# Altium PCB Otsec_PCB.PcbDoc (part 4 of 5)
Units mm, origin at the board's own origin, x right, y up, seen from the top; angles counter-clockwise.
Board outline 170 x 120 mm, 3 copper layers (Top Layer, Internal Plane 1, Bottom Layer), stack 1.608 mm thick; 1624 components, 0 nets, 5478 pads, 0 vias.
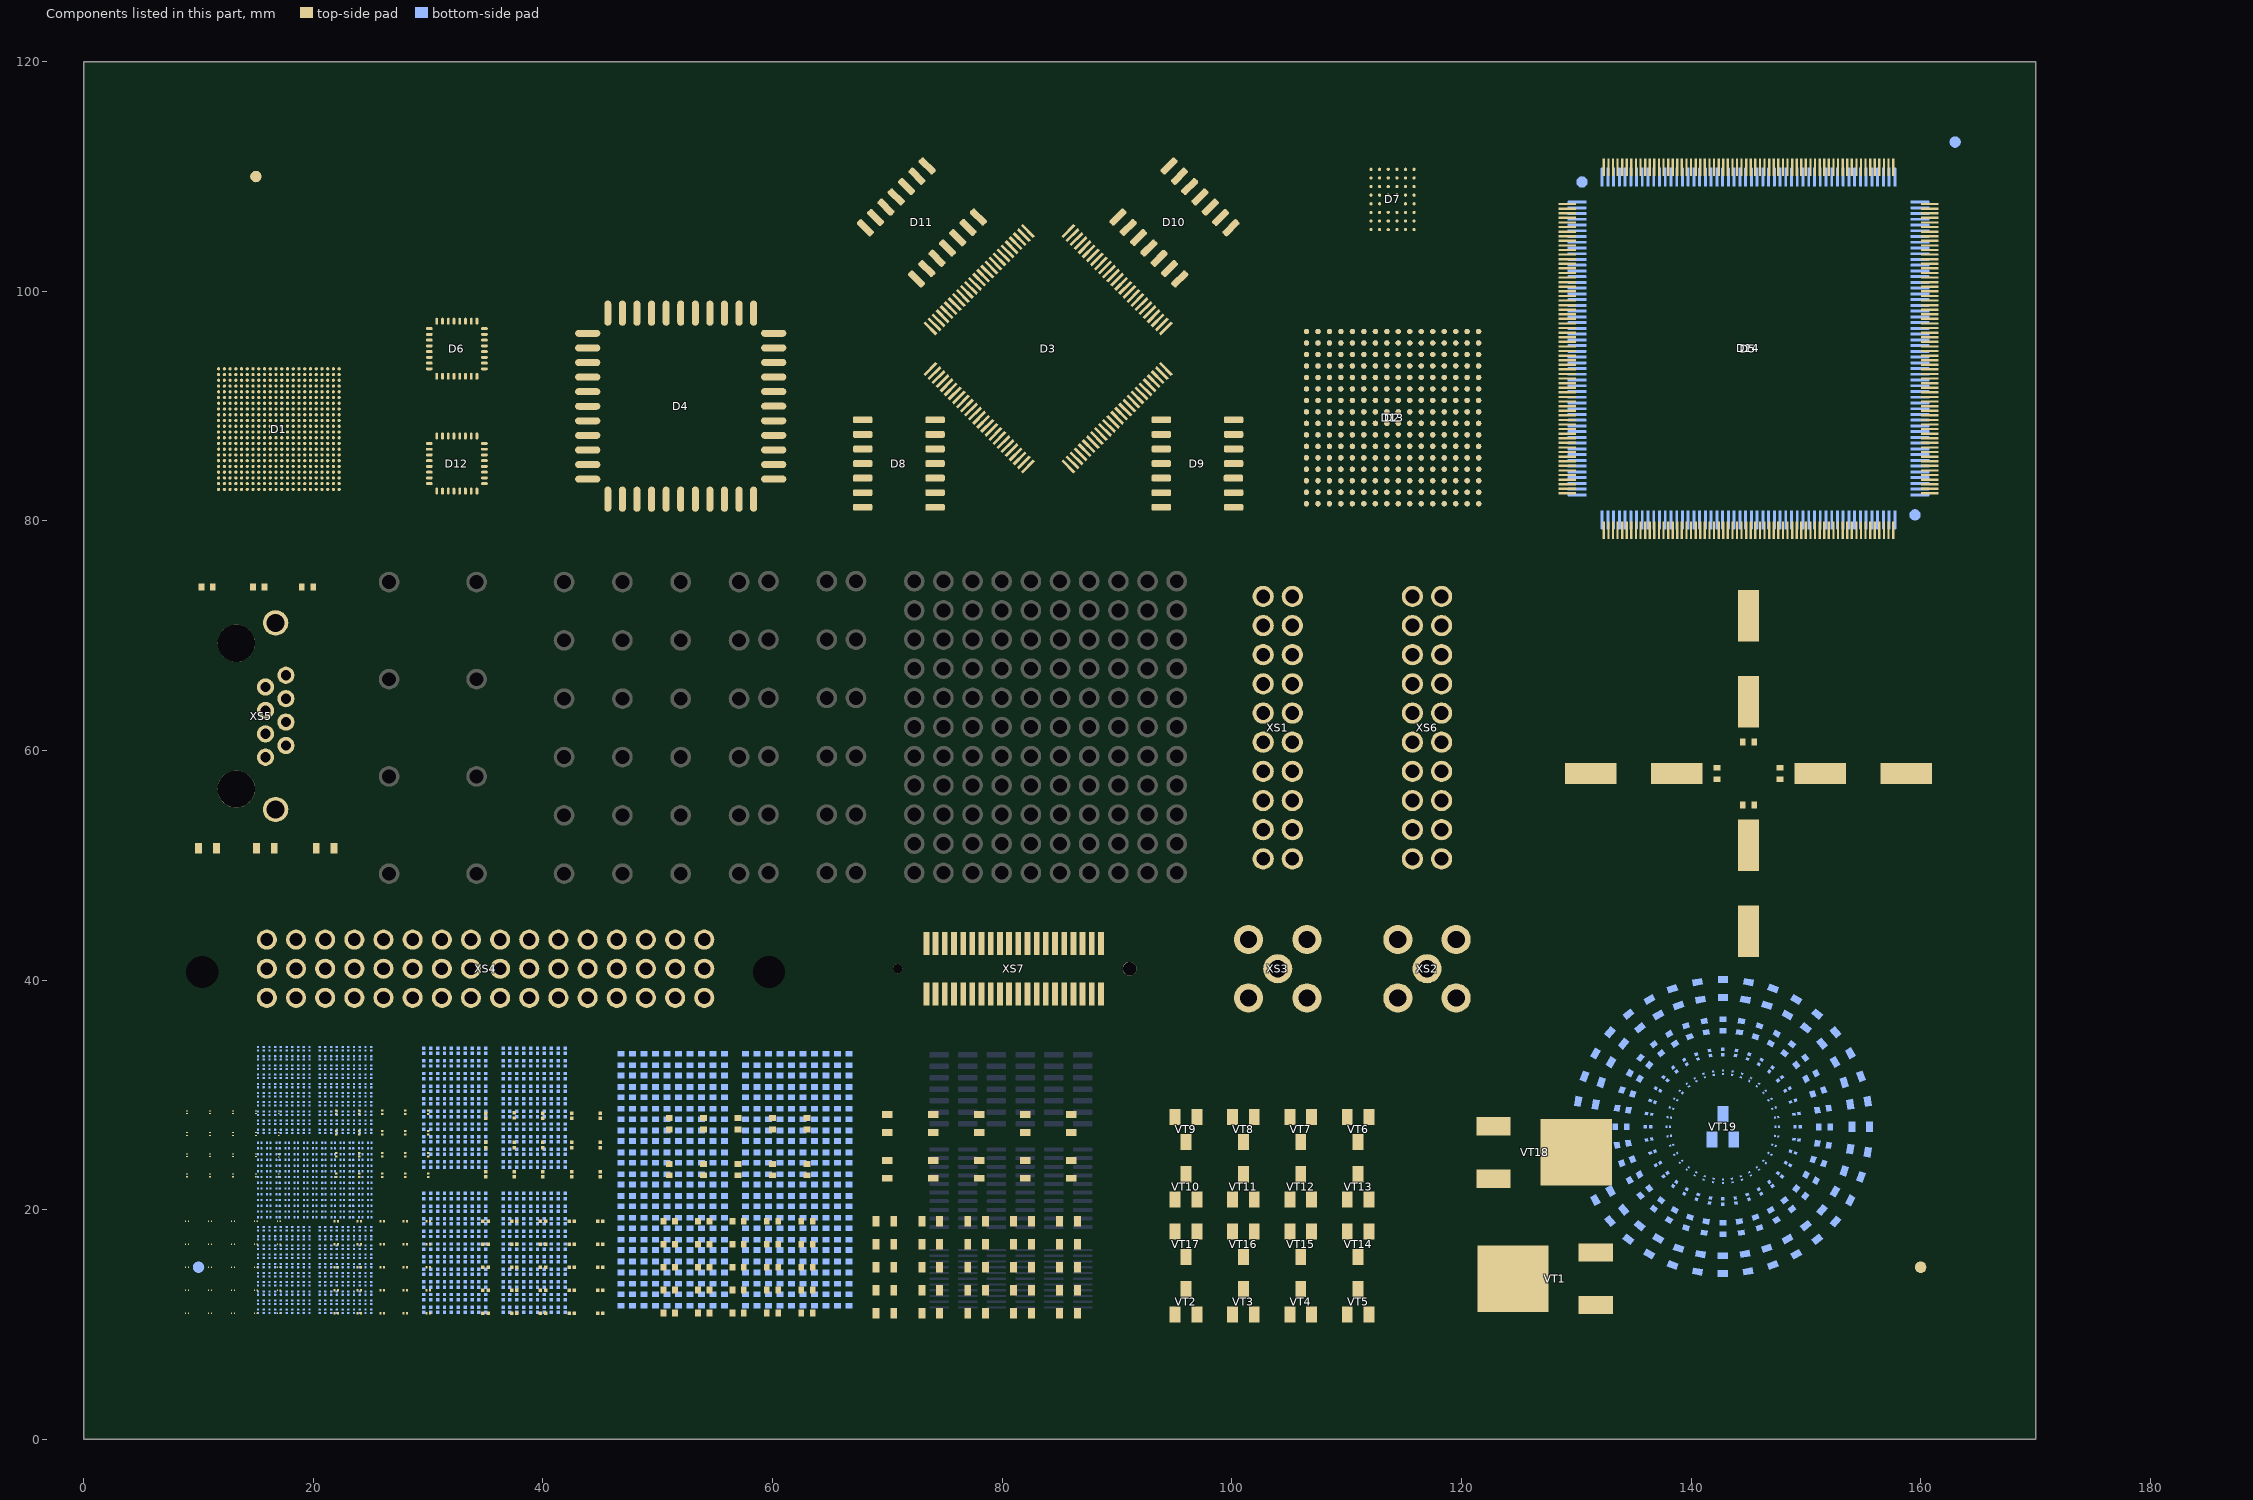
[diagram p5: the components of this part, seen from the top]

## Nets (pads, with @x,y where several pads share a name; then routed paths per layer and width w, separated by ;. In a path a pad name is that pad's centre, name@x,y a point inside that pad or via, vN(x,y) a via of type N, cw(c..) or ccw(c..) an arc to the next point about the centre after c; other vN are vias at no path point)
pads on no net: C1.1 C1.2 C2.1 C2.2 C3.1 C3.2 C4.1 C4.2 D1.1 D1.2 D1.3 D1.4 D1.5 D1.6 D1.7 D1.8 D1.9 D1.10 D1.11 D1.12 D1.13 D1.14 D1.15 D1.16 D1.17 D1.18 D1.19 D1.20 D1.21 D1.22 D1.23 D1.24 D1.25 D1.26 D1.27 D1.28 D1.29 D1.30 D1.31 D1.32 D1.33 D1.34 D1.35 D1.36 D1.37 D1.38 D1.39 D1.40 D1.41 D1.42 D1.43 D1.44 D1.45 D1.46 D1.47 D1.48 D1.49 D1.50 D1.51 D1.52 D1.53 D1.54 D1.55 D1.56 D1.57 D1.58 D1.59 D1.60 D1.61 D1.62 D1.63 D1.64 D1.65 D1.66 D1.67 D1.68 D1.69 D1.70 D1.71 D1.72 D1.73 D1.74 D1.75 D1.76 D1.77 D1.78 D1.79 D1.80 D1.81 D1.82 D1.83 D1.84 D1.85 D1.86 D1.87 D1.88 D1.89 D1.90 D1.91 D1.92 D1.93 D1.94 D1.95 D1.96 D1.97 D1.98 D1.99 D1.100 D1.101 D1.102 D1.103 D1.104 D1.105 D1.106 D1.107 D1.108 D1.109 D1.110 D1.111 D1.112 D1.113 D1.114 D1.115 D1.116 D1.117 D1.118 D1.119 D1.120 D1.121 D1.122 D1.123 D1.124 D1.125 D1.126 D1.127 D1.128 D1.129 D1.130 D1.131 D1.132 D1.133 D1.134 D1.135 D1.136 D1.137 D1.138 D1.139 D1.140 D1.141 D1.142 D1.143 D1.144 D1.145 D1.146 D1.147 D1.148 D1.149 D1.150 D1.151 D1.152 D1.153 D1.154 D1.155 D1.156 D1.157 D1.158 D1.159 D1.160 D1.161 D1.162 D1.163 D1.164 D1.165 D1.166 D1.167 D1.168 D1.169 D1.170 D1.171 D1.172 D1.173 D1.174 D1.175 D1.176 D1.177 D1.178 D1.179 D1.180 D1.181 D1.182 D1.183 D1.184 D1.185 D1.186 D1.187 D1.188 D1.189 D1.190 D1.191 D1.192 D1.193 D1.194 D1.195 D1.196 D1.197 D1.198 D1.199 D1.200 D1.201 D1.202 D1.203 D1.204 D1.205 D1.206 D1.207 D1.208 D1.209 D1.210 D1.211 D1.212 D1.213 D1.214 D1.215 D1.216 D1.217 D1.218 D1.219 D1.220 D1.221 D1.222 D1.223 D1.224 D1.225 D1.226 D1.227 D1.228 D1.229 D1.230 D1.231 D1.232 D1.233 D1.234 D1.235 D1.236 D1.237 D1.238 D1.239 D1.240 D1.241 D1.242 D1.243 D1.244 D1.245 D1.246 D1.247 D1.248 D1.249 D1.250 D1.251 D1.252 D1.253 D1.254 D1.255 D1.256 D1.257 D1.258 D1.259 D1.260 D1.261 D1.262 D1.263 D1.264 D1.265 D1.266 D1.267 D1.268 D1.269 D1.270 D1.271 D1.272 D1.273 D1.274 D1.275 D1.276 D1.277 D1.278 D1.279 D1.280 D1.281 D1.282 D1.283 D1.284 D1.285 D1.286 D1.287 D1.288 D1.289 D1.290 D1.291 D1.292 D1.293 D1.294 D1.295 D1.296 D1.297 D1.298 D1.299 D1.300 D1.301 D1.302 D1.303 D1.304 D1.305 D1.306 D1.307 D1.308 D1.309 D1.310 D1.311 D1.312 D1.313 D1.314 D1.315 D1.316 D1.317 D1.318 D1.319 D1.320 D1.321 D1.322 D1.323 D1.324 D1.325 D1.326 D1.327 D1.328 D1.329 D1.330 D1.331 D1.332 D1.333 D1.334 D1.335 D1.336 D1.337 D1.338 D1.339 D1.340 D1.341 D1.342 D1.343 D1.344 D1.345 D1.346 D1.347 D1.348 D1.349 D1.350 D1.351 D1.352 D1.353 D1.354 D1.355 D1.356 D1.357 D1.358 D1.359 D1.360 D1.361 D1.362 D1.363 D1.364 D1.365 D1.366 D1.367 D1.368 D1.369 D1.370 D1.371 D1.372 D1.373 D1.374 D1.375 D1.376 D1.377 D1.378 D1.379 D1.380 D1.381 D1.382 D1.383 D1.384 D1.385 D1.386 D1.387 D1.388 D1.389 D1.390 D1.391 D1.392 D1.393 D1.394 D1.395 D1.396 D1.397 D1.398 D1.399 D1.400 D1.401 D1.402 D1.403 D1.404 D1.405 D1.406 D1.407 D1.408 D1.409 D1.410 D1.411 D1.412 D1.413 D1.414 D1.415 D1.416 D1.417 D1.418 D1.419 D1.420 D1.421 D1.422 D1.423 D1.424 D1.425 D1.426 D1.427 D1.428 D1.429 D1.430 D1.431 D1.432 D1.433 D1.434 D1.435 D1.436 D1.437 D1.438 D1.439 D1.440 D1.441 D1.442 D1.443 D1.444 D1.445 D1.446 D1.447 D1.448 D1.449 D1.450 D1.451 D1.452 D1.453 D1.454 D1.455 D1.456 D1.457 D1.458 D1.459 D1.460 D1.461 D1.462 D1.463 D1.464 D1.465 D1.466 D1.467 D1.468 D1.469 D1.470 D1.471 D1.472 D1.473 D1.474 D1.475 D1.476 D1.477 D1.478 D1.479 D1.480 D1.481 D1.482 D1.483 D1.484 D2.1 D2.2 D2.3 D2.4 D2.5 D2.6 D2.7 D2.8 D2.9 D2.10 D2.11 D2.12 D2.13 D2.14 D2.15 D2.16 D2.17 D2.18 D2.19 D2.20 D2.21 D2.22 D2.23 D2.24 D2.25 D2.26 D2.27 D2.28 D2.29 D2.30 D2.31 D2.32 D2.33 D2.34 D2.35 D2.36 D2.37 D2.38 D2.39 D2.40 D2.41 D2.42 D2.43 D2.44 D2.45 D2.46 D2.47 D2.48 D2.49 D2.50 D2.51 D2.52 D2.53 D2.54 D2.55 D2.56 D2.57 D2.58 D2.59 D2.60 D2.61 D2.62 D2.63 D2.64 D2.65 D2.66 D2.67 D2.68 D2.69 D2.70 D2.71 D2.72 D2.73 D2.74 D2.75 D2.76 D2.77 D2.78 D2.79 D2.80 D2.81 D2.82 D2.83 D2.84 D2.85 D2.86 D2.87 D2.88 D2.89 D2.90 D2.91 D2.92 D2.93 D2.94 D2.95 D2.96 D2.97 D2.98 D2.99 D2.100 D2.101 D2.102 D2.103 D2.104 D2.105 D2.106 D2.107 D2.108 D2.109 D2.110 D2.111 D2.112 D2.113 D2.114 D2.115 D2.116 D2.117 D2.118 D2.119 D2.120 D2.121 D2.122 D2.123 D2.124 D2.125 D2.126 D2.127 D2.128 D2.129 D2.130 D2.131 D2.132 D2.133 D2.134 D2.135 D2.136 D2.137 D2.138 D2.139 D2.140 D2.141 D2.142 D2.143 D2.144 D2.145 D2.146 D2.147 D2.148 D2.149 D2.150 D2.151 D2.152 D2.153 D2.154 D2.155 D2.156 D2.157 D2.158 D2.159 D2.160 D2.161 D2.162 D2.163 D2.164 D2.165 D2.166 D2.167 D2.168 D2.169 D2.170 D2.171 D2.172 D2.173 D2.174 D2.175 D2.176 D2.177 D2.178 D2.179 D2.180 D2.181 D2.182 D2.183 D2.184 D2.185 D2.186 D2.187 D2.188 D2.189 D2.190 D2.191 D2.192 D2.193 D2.194 D2.195 D2.196 D2.197 D2.198 D2.199 D2.200 D2.201 D2.202 D2.203 D2.204 D2.205 D2.206 D2.207 D2.208 D2.209 D2.210 D2.211 D2.212 D2.213 D2.214 D2.215 D2.216 D2.217 D2.218 D2.219 D2.220 D2.221 D2.222 D2.223 D2.224 D2.225 D2.226 D2.227 D2.228 D2.229 D2.230 D2.231 D2.232 D2.233 D2.234 D2.235 D2.236 D2.237 D2.238 D2.239 D2.240 D2.241 D2.242 D2.243 D2.244 D2.245 D2.246 D2.247 D2.248 D2.249 D2.250 D2.251 D2.252 D2.253 D2.254 D2.255 D2.256 D3.1 D3.2 D3.3 D3.4 D3.5 D3.6 D3.7 D3.8 D3.9 D3.10 D3.11 D3.12 D3.13 D3.14 D3.15 D3.16 D3.17 D3.18 D3.19 D3.20 D3.21 D3.22 D3.23 D3.24 D3.25 D3.26 D3.27 D3.28 D3.29 D3.30 D3.31 D3.32 D3.33 D3.34 D3.35 D3.36 D3.37 D3.38 D3.39 D3.40 D3.41 D3.42 D3.43 D3.44 D3.45 D3.46 D3.47 D3.48 D3.49 D3.50 D3.51 D3.52 D3.53 D3.54 D3.55 D3.56 D3.57 D3.58 D3.59 D3.60 D3.61 D3.62 D3.63 D3.64 D3.65 D3.66 D3.67 D3.68 D3.69 D3.70 D3.71 D3.72 D3.73 D3.74 D3.75 D3.76 D3.77 D3.78 D3.79 D3.80 D3.81 D3.82 D3.83 D3.84 D3.85 D3.86 D3.87 D3.88 D3.89 D3.90 D3.91 D3.92 D3.93 D3.94 D3.95 D3.96 D3.97 D3.98 D3.99 D3.100 D4.1 D4.2 D4.3 D4.4 D4.5 D4.6 D4.7 D4.8 D4.9 D4.10 D4.11 D4.12 D4.13 D4.14 D4.15 D4.16 D4.17 D4.18 D4.19 D4.20 D4.21 D4.22 D4.23 D4.24 D4.25 D4.26 D4.27 D4.28 D4.29 D4.30 D4.31 D4.32 D4.33 D4.34 D4.35 D4.36 D4.37 D4.38 D4.39 D4.40 D4.41 D4.42 D4.43 D4.44 D5.1 D5.2 D5.3 D5.4 D5.5 D5.6 D5.7 D5.8 D5.9 D5.10 D5.11 D5.12 D5.13 D5.14 D5.15 D5.16 D5.17 D5.18 D5.19 D5.20 D5.21 D5.22 D5.23 D5.24 D5.25 D5.26 D5.27 D5.28 D5.29 D5.30 D5.31 D5.32 D5.33 D5.34 D5.35 D5.36 D5.37 D5.38 D5.39 D5.40 D5.41 D5.42 D5.43 D5.44 D5.45 D5.46 D5.47 D5.48 D5.49 D5.50 D5.51 D5.52 D5.53 D5.54 D5.55 D5.56 D5.57 D5.58 D5.59 D5.60 D5.61 D5.62 D5.63 D5.64 D5.65 D5.66 D5.67 D5.68 D5.69 D5.70 D5.71 D5.72 D5.73 D5.74 D5.75 D5.76 D5.77 D5.78 D5.79 D5.80 D5.81 D5.82 D5.83 D5.84 D5.85 D5.86 D5.87 D5.88 D5.89 D5.90 D5.91 D5.92 D5.93 D5.94 D5.95 D5.96 D5.97 D5.98 D5.99 D5.100 D5.101 D5.102 D5.103 D5.104 D5.105 D5.106 D5.107 D5.108 D5.109 D5.110 D5.111 D5.112 D5.113 D5.114 D5.115 D5.116 D5.117 D5.118 D5.119 D5.120 D5.121 D5.122 D5.123 D5.124 D5.125 D5.126 D5.127 D5.128 D5.129 D5.130 D5.131 D5.132 D5.133 D5.134 D5.135 D5.136 D5.137 D5.138 D5.139 D5.140 D5.141 D5.142 D5.143 D5.144 D5.145 D5.146 D5.147 D5.148 D5.149 D5.150 D5.151 D5.152 D5.153 D5.154 D5.155 D5.156 D5.157 D5.158 D5.159 D5.160 D5.161 D5.162 D5.163 D5.164 D5.165 D5.166 D5.167 D5.168 D5.169 D5.170 D5.171 D5.172 D5.173 D5.174 D5.175 D5.176 D5.177 D5.178 D5.179 D5.180 D5.181 D5.182 D5.183 D5.184 D5.185 D5.186 D5.187 D5.188 D5.189 D5.190 D5.191 D5.192 D5.193 D5.194 D5.195 D5.196 D5.197 D5.198 D5.199 D5.200 D5.201 D5.202 D5.203 D5.204 D5.205 D5.206 D5.207 D5.208 D5.209 D5.210 D5.211 D5.212 D5.213 D5.214 D5.215 D5.216 D5.217 D5.218 D5.219 D5.220 D5.221 D5.222 D5.223 D5.224 D5.225 D5.226 D5.227 D5.228 D5.229 D5.230 D5.231 D5.232 D5.233 D5.234 D5.235 D5.236 D5.237 D5.238 D5.239 D5.240 D5.241 D5.242 D5.243 D5.244 D5.245 D5.246 D5.247 D5.248 D5.249 D5.250 D5.251 D5.252 D5.253 D5.254 D5.255 D5.256 D6.1 D6.2 D6.3 D6.4 D6.5 D6.6 D6.7 D6.8 D6.9 D6.10 D6.11 D6.12 D6.13 D6.14 D6.15 D6.16 D6.17 D6.18 D6.19 D6.20 D6.21 D6.22 D6.23 D6.24 D6.25 D6.26 D6.27 D6.28 D6.29 D6.30 D6.31 D6.32 D7.1 D7.2 D7.3 D7.4 D7.5 D7.6 D7.7 D7.8 D7.9 D7.10 D7.11 D7.12 D7.13 D7.14 D7.15 D7.16 D7.17 D7.18 D7.19 D7.20 D7.21 D7.22 D7.23 D7.24 D7.25 D7.26 D7.27 D7.28 D7.29 D7.30 D7.31 D7.32 D7.33 D7.34 D7.35 D7.36 D7.37 D7.38 D7.39 D7.40 D7.41 D7.42 D7.43 D7.44 D7.45 D7.46 D8.1 D8.2 D8.3 D8.4 D8.5 D8.6 D8.7 D8.8 D8.9 D8.10 D8.11 D8.12 D8.13 D8.14 D9.1 D9.2 D9.3 D9.4 D9.5 D9.6 D9.7 D9.8 D9.9 D9.10 D9.11 D9.12 D9.13 D9.14 D10.1 D10.2 D10.3 D10.4 D10.5 D10.6 D10.7 D10.8 D10.9 D10.10 D10.11 D10.12 D10.13 D10.14 D11.1 D11.2 D11.3 D11.4 D11.5 D11.6 D11.7 D11.8 D11.9 D11.10 D11.11 D11.12 D11.13 D11.14 D12.1 D12.2 D12.3 D12.4 D12.5 D12.6 D12.7 D12.8 D12.9 D12.10 D12.11 D12.12 D12.13 D12.14 D12.15 D12.16 D12.17 D12.18 D12.19 D12.20 D12.21 D12.22 D12.23 D12.24 D12.25 D12.26 D12.27 D12.28 D12.29 D12.30 D12.31 D12.32 D13.1 D13.2 D13.3 D13.4 D13.5 D13.6 D13.7 D13.8 D13.9 D13.10 D13.11 D13.12 D13.13 D13.14 D13.15 D13.16 D13.17 D13.18 D13.19 D13.20 D13.21 D13.22 D13.23 D13.24 D13.25 D13.26 D13.27 D13.28 D13.29 D13.30 D13.31 D13.32 D13.33 D13.34 D13.35 D13.36 D13.37 D13.38 D13.39 D13.40 D13.41 D13.42 D13.43 D13.44 D13.45 D13.46 D13.47 D13.48 D13.49 D13.50 D13.51 D13.52 D13.53 D13.54 D13.55 D13.56 D13.57 D13.58 D13.59 D13.60 D13.61 D13.62 D13.63 D13.64 D13.65 D13.66 D13.67 D13.68 D13.69 D13.70 D13.71 D13.72 D13.73 D13.74 D13.75 D13.76 D13.77 D13.78 D13.79 D13.80 D13.81 D13.82 D13.83 D13.84 D13.85 D13.86 D13.87 D13.88 D13.89 D13.90 D13.91 D13.92 D13.93 D13.94 D13.95 D13.96 D13.97 D13.98 D13.99 D13.100 D13.101 D13.102 D13.103 D13.104 D13.105 D13.106 D13.107 D13.108 D13.109 D13.110 D13.111 D13.112 D13.113 D13.114 D13.115 D13.116 D13.117 D13.118 D13.119 D13.120 D13.121 D13.122 D13.123 D13.124 D13.125 D13.126 D13.127 D13.128 D13.129 D13.130 D13.131 D13.132 D13.133 D13.134 D13.135 D13.136 D13.137 D13.138 D13.139 D13.140 D13.141 D13.142 D13.143 D13.144 D13.145 D13.146 D13.147 D13.148 D13.149 D13.150 D13.151 D13.152 D13.153 D13.154 D13.155 D13.156 D13.157 D13.158 D13.159 D13.160 D13.161 D13.162 D13.163 D13.164 D13.165 D13.166 D13.167 D13.168 D13.169 D13.170 D13.171 D13.172 D13.173 D13.174 D13.175 D13.176 D13.177 D13.178 D13.179 D13.180 D13.181 D13.182 D13.183 D13.184 D13.185 D13.186 D13.187 D13.188 D13.189 D13.190 D13.191 D13.192 D13.193 D13.194 D13.195 D13.196 D13.197 D13.198 D13.199 D13.200 D13.201 D13.202 D13.203 D13.204 D13.205 D13.206 D13.207 D13.208 D13.209 D13.210 D13.211 D13.212 D13.213 D13.214 D13.215 D13.216 D13.217 D13.218 D13.219 D13.220 D13.221 D13.222 D13.223 D13.224 D13.225 D13.226 D13.227 D13.228 D13.229 D13.230 D13.231 D13.232 D13.233 D13.234 D13.235 D13.236 D13.237 D13.238 D13.239 D13.240 D13.241 D13.242 D13.243 D13.244 D13.245 D13.246 D13.247 D13.248 D13.249 D13.250 D13.251 D13.252 D13.253 D13.254 D13.255 D13.256 D14. D14.1 D14.2 D14.3 D14.4 D14.5 D14.6 D14.7 D14.8 D14.9 D14.10 D14.11 D14.12 D14.13 D14.14 D14.15 D14.16 D14.17 D14.18 D14.19 D14.20 D14.21 D14.22 D14.23 D14.24 D14.25 D14.26 D14.27 D14.28 D14.29 D14.30 D14.31 D14.32 D14.33 D14.34 D14.35 D14.36 D14.37 D14.38 D14.39 D14.40 D14.41 D14.42 D14.43 D14.44 D14.45 D14.46 D14.47 D14.48 D14.49 D14.50 D14.51 D14.52 D14.53 D14.54 D14.55 D14.56 D14.57 D14.58 D14.59 D14.60 D14.61 D14.62 D14.63 D14.64 D14.65 D14.66 D14.67 D14.68 D14.69 D14.70 D14.71 D14.72 D14.73 D14.74 D14.75 D14.76 D14.77 D14.78 D14.79 D14.80 D14.81 D14.82 D14.83 D14.84 D14.85 D14.86 D14.87 D14.88 D14.89 D14.90 D14.91 D14.92 D14.93 D14.94 D14.95 D14.96 D14.97 D14.98 D14.99 D14.100 D14.101 D14.102 D14.103 D14.104 D14.105 D14.106 D14.107 D14.108 D14.109 D14.110 D14.111 D14.112 D14.113 D14.114 D14.115 D14.116 D14.117 D14.118 D14.119 D14.120 D14.121 D14.122 D14.123 D14.124 D14.125 D14.126 D14.127 D14.128 D14.129 D14.130 D14.131 D14.132 D14.133 D14.134 D14.135 D14.136 D14.137 D14.138 D14.139 D14.140 D14.141 D14.142 D14.143 D14.144 D14.145 D14.146 D14.147 D14.148 D14.149 D14.150 D14.151 D14.152 D14.153 D14.154 D14.155 D14.156 D14.157 D14.158 D14.159 D14.160 D14.161 D14.162 D14.163 D14.164 D14.165 D14.166 D14.167 D14.168 D14.169 D14.170 D14.171 D14.172 D14.173 D14.174 D14.175 D14.176 D14.177 D14.178 D14.179 D14.180 D14.181 D14.182 D14.183 D14.184 D14.185 D14.186 D14.187 D14.188 D14.189 D14.190 D14.191 D14.192 D14.193 D14.194 D14.195 D14.196 D14.197 D14.198 D14.199 D14.200 D14.201 D14.202 D14.203 D14.204 D14.205 D14.206 D14.207 D14.208 FID1.1 FID2.1 FID3.1 FID4.1 R1.1 R1.2 R2.1 R2.2 R3.1 R3.2 R4.1 R4.2 R5.1 R5.2 R6.1 R6.2 R7.1 R7.2 R8.1 R8.2 R9.1 R9.2 R10.1 R10.2 R11.1 R11.2 R12.1 R12.2 R13.1 R13.2 R14.1 R14.2 R15.1 R15.2 R16.1 R16.2 R17.1 R17.2 R18.1 R18.2 R19.1 R19.2 R20.1 R20.2 R21.1 R21.2 R22.1 R22.2 R23.1 R23.2 R24.1 R24.2 R25.1 R25.2 R26.1 R26.2 R27.1 R27.2 R28.1 R28.2 R29.1 R29.2 R30.1 R30.2 R31.1 R31.2 R32.1 R32.2 R33.1 R33.2 R34.1 R34.2 R35.1 R35.2 R36.1 R36.2 R37.1 R37.2 R38.1 R38.2 R39.1 R39.2 R40.1 R40.2 R41.1 R41.2 R42.1 R42.2 R43.1 R43.2 R44.1 R44.2 R45.1 R45.2 R46.1 R46.2 R47.1 R47.2 R48.1 R48.2 R49.1 R49.2 R50.1 R50.2 R51.1 R51.2 R52.1 R52.2 R53.1 R53.2 R54.1 R54.2 R55.1 R55.2 R56.1 R56.2 R57.1 R57.2 R58.1 R58.2 R59.1 R59.2 R60.1 R60.2 R61.1 R61.2 R62.1 R62.2 R63.1 R63.2 R64.1 R64.2 R65.1 R65.2 R66.1 R66.2 R67.1 R67.2 R68.1 R68.2 R69.1 R69.2 R70.1 R70.2 R71.1 R71.2 R72.1 R72.2 R73.1 R73.2 R74.1 R74.2 R75.1 R75.2 R76.1 R76.2 R77.1 R77.2 R78.1 R78.2 R79.1 R79.2 R80.1 R80.2 R81.1 R81.2 R82.1 R82.2 R83.1 R83.2 R84.1 R84.2 R85.1 R85.2 R86.1 R86.2 R87.1 R87.2 R88.1 R88.2 R89.1 R89.2 R90.1 R90.2 R91.1 R91.2 R92.1 R92.2 R93.1 R93.2 R94.1 R94.2 R95.1 R95.2 R96.1 R96.2 R97.1 R97.2 R98.1 R98.2 R99.1 R99.2 R100.1 R100.2 R101.1 R101.2 R102.1 R102.2 R103.1 R103.2 R104.1 R104.2 R105.1 R105.2 R106.1 R106.2 R107.1 R107.2 R108.1 R108.2 R109.1 R109.2 R110.1 R110.2 R111.1 R111.2 R112.1 R112.2 R113.1 R113.2 R114.1 R114.2 R115.1 R115.2 R116.1 R116.2 R117.1 R117.2 R118.1 R118.2 R119.1 R119.2 R120.1 R120.2 R121.1 R121.2 R122.1 R122.2 R123.1 R123.2 R124.1 R124.2 R125.1 R125.2 R126.1 R126.2 R127.1 R127.2 R128.1 R128.2 R129.1 R129.2 R130.1 R130.2 R131.1 R131.2 R132.1 R132.2 R133.1 R133.2 R134.1 R134.2 R135.1 R135.2 R136.1 R136.2 R137.1 R137.2 R138.1 R138.2 R139.1 R139.2 R140.1 R140.2 R141.1 R141.2 R142.1 R142.2 R143.1 R143.2 R144.1 R144.2 R145.1 R145.2 R146.1 R146.2 R147.1 R147.2 R148.1 R148.2 R149.1 R149.2 R150.1 R150.2 R151.1 R151.2 R152.1 R152.2 R153.1 R153.2 R154.1 R154.2 R155.1 R155.2 R156.1 R156.2 R157.1 R157.2 R158.1 R158.2 R159.1 R159.2 R160.1 R160.2 R161.1 R161.2 R162.1 R162.2 R163.1 R163.2 R164.1 R164.2 R165.1 R165.2 R166.1 R166.2 R167.1 R167.2 R168.1 R168.2 R169.1 R169.2 R170.1 R170.2 R171.1 R171.2 R172.1 R172.2 R173.1 R173.2 R174.1 R174.2 R175.1 R175.2 R176.1 R176.2 R177.1 R177.2 R178.1 R178.2 R179.1 R179.2 R180.1 R180.2 R181.1 R181.2 R182.1 R182.2 R183.1 R183.2 R184.1 R184.2 R185.1 R185.2 R186.1 R186.2 R187.1 R187.2 R188.1 R188.2 R189.1 R189.2 R190.1 R190.2 R191.1 R191.2 R192.1 R192.2 R193.1 R193.2 R194.1 R194.2 R195.1 R195.2 R196.1 R196.2 R197.1 R197.2 R198.1 R198.2 R199.1 R199.2 R200.1 R200.2 R201.1 R201.2 R202.1 R202.2 R203.1 R203.2 R204.1 R204.2 R205.1 R205.2 R206.1 R206.2 R207.1 R207.2 R208.1 R208.2 R209.1 R209.2 R210.1 R210.2 R211.1 R211.2 R211_1.1 R211_1.2 R211_1_1.1 R211_1_1.2 R211_2.1 R211_2.2 R211_3.1 R211_3.2 R211_3_1.1 R211_3_1.2 R211_3_1_1.1 R211_3_1_1.2 R211_3_2.1 R211_3_2.2 R212.1 R212.2 R212_1.1 R212_1.2 R212_1_1.1 R212_1_1.2 R212_2.1 R212_2.2 R212_3.1 R212_3.2 R212_3_1.1 R212_3_1.2 R212_3_1_1.1 R212_3_1_1.2 R212_3_2.1 R212_3_2.2 R213.1 R213.2 R213_1.1 R213_1.2 R213_1_1.1 R213_1_1.2 R213_2.1 R213_2.2 R213_3.1 R213_3.2 R213_3_1.1 R213_3_1.2 R213_3_1_1.1 R213_3_1_1.2 R213_3_2.1 R213_3_2.2 R214.1 R214.2 R214_1.1 R214_1.2 R214_1_1.1 R214_1_1.2 R214_2.1 R214_2.2 R214_3.1 R214_3.2 R214_3_1.1 R214_3_1.2 R215.1 R215.2 R215_1.1 R215_1.2 R215_1_1.1 R215_1_1.2 R215_2.1 R215_2.2 R215_3.1 R215_3.2 R215_3_1.1 R215_3_1.2 R216.1 R216.2 R216_1.1 R216_1.2 R216_1_1.1 R216_1_1.2 R216_2.1 R216_2.2 R216_3.1 R216_3.2 R217.1 R217.2 R217_1.1 R217_1.2 R217_1_1.1 R217_1_1.2 R217_2.1 R217_2.2 R217_3.1 R217_3.2 R218.1 R218.2 R218_1.1 R218_1.2 R218_1_1.1 R218_1_1.2 R218_2.1 R218_2.2 R218_3.1 R218_3.2 R219.1 R219.2 R219_1.1 R219_1.2 R219_1_1.1 R219_1_1.2 R219_2.1 R219_2.2 R219_3.1 R219_3.2 R220.1 R220.2 R220_1.1 R220_1.2 R220_1_1.1 R220_1_1.2 R220_2.1 R220_2.2 R220_3.1 R220_3.2 R220_3_1.1 R220_3_1.2 R220_3_1_1.1 R220_3_1_1.2 R220_3_2.1 R220_3_2.2 R221.1 R221.2 R221_1.1 R221_1.2 R221_1_1.1 R221_1_1.2 R221_2.1 R221_2.2 R221_3.1 R221_3.2 R221_3_1.1 R221_3_1.2 R222.1 R222.2 R222_1.1 R222_1.2 R222_1_1.1 R222_1_1.2 R222_2.1 R222_2.2 R222_3.1 R222_3.2 R223.1 R223.2 R223_1.1 R223_1.2 R223_1_1.1 R223_1_1.2 R223_2.1 R223_2.2 R223_3.1 R223_3.2 R224.1 R224.2 R224_1.1 R224_1.2 R224_1_1.1 R224_1_1.2 R224_2.1 R224_2.2 R224_3.1 R224_3.2 R224_3_1.1 R224_3_1.2 R225.1 R225.2 R225_1.1 R225_1.2 R225_1_1.1 R225_1_1.2 R225_2.1 R225_2.2 R225_3.1 R225_3.2 R225_3_1.1 R225_3_1.2 R226.1 R226.2 R226_1.1 R226_1.2 R226_1_1.1 R226_1_1.2 R226_2.1 R226_2.2 R226_3.1 R226_3.2 R226_3_1.1 R226_3_1.2 R227.1 R227.2 R227_1.1 R227_1.2 R227_1_1.1 R227_1_1.2 R227_2.1 R227_2.2 R227_3.1 R227_3.2 R227_3_1.1 R227_3_1.2 R228.1 R228.2 R228_1.1 R228_1.2 R228_1_1.1 R228_1_1.2 R228_2.1 R228_2.2 R228_3.1 R228_3.2 R228_3_1.1 R228_3_1.2 R229.1 R229.2 R229_1.1 R229_1.2 R229_1_1.1 R229_1_1.2 R229_2.1 R229_2.2 R229_3.1 R229_3.2 R229_3_1.1 R229_3_1.2 R230.1 R230.2 R230_1.1 R230_1.2 R230_1_1.1 R230_1_1.2 R230_2.1 R230_2.2 R230_3.1 R230_3.2 R230_3_1.1 R230_3_1.2 R231.1 R231.2 R231_1.1 R231_1.2 R231_1_1.1 R231_1_1.2 R231_2.1 R231_2.2 R231_3.1 R231_3.2 R232.1 R232.2 R232_1.1 R232_1.2 R232_1_1.1 R232_1_1.2 R232_2.1 R232_2.2 R232_3.1 R232_3.2 R233.1 R233.2 R233_1.1 R233_1.2 R233_1_1.1 R233_1_1.2 R233_2.1 R233_2.2 R233_3.1 R233_3.2 R234.1 R234.2 R234_1.1 R234_1.2 R234_1_1.1 R234_1_1.2 R234_2.1 R234_2.2 R234_3.1 R234_3.2 R235.1 R235.2 R235_1.1 R235_1.2 R235_1_1.1 R235_1_1.2 R235_2.1 R235_2.2 R235_3.1 R235_3.2 R236.1 R236.2 R236_1.1 R236_1.2 R236_1_1.1 R236_1_1.2 R236_2.1 R236_2.2 R236_3.1 R236_3.2 R236_3_1.1 R236_3_1.2 R237.1 R237.2 R237_1.1 R237_1.2 R237_1_1.1 R237_1_1.2 R237_2.1 R237_2.2 R237_3.1 R237_3.2 R237_3_1.1 R237_3_1.2 R238.1 R238.2 R238_1.1 R238_1.2 R238_1_1.1 R238_1_1.2 R238_2.1 R238_2.2 R238_3.1 R238_3.2 R238_3_1.1 R238_3_1.2 R239.1 R239.2 R239_1.1 R239_1.2 R239_1_1.1 R239_1_1.2 R239_2.1 R239_2.2 R239_3.1 R239_3.2 R240.1 R240.2 R240_1.1 R240_1.2 R240_1_1.1 R240_1_1.2 R240_2.1 R240_2.2 R240_3.1 R240_3.2 R240_3_1.1 R240_3_1.2 R241.1 R241.2 R241_1.1 R241_1.2 R241_1_1.1 R241_1_1.2 R241_2.1 R241_2.2 R241_3.1 R241_3.2 R241_3_1.1 R241_3_1.2 R241_3_1_1.1 R241_3_1_1.2 R241_3_2.1 R241_3_2.2 R242.1 R242.2 R242_1.1 R242_1.2 R242_1_1.1 R242_1_1.2 R242_2.1 R242_2.2 R242_3.1 R242_3.2 R242_3_1.1 R242_3_1.2 R242_3_1_1.1 R242_3_1_1.2 R242_3_2.1 R242_3_2.2 R243.1 R243.2 R243_1.1 R243_1.2 R243_1_1.1 R243_1_1.2 R243_2.1 R243_2.2 R243_3.1 R243_3.2 R243_3_1.1 R243_3_1.2 R244.1 R244.2 R244_1.1 R244_1.2 R244_1_1.1 R244_1_1.2 R244_2.1 R244_2.2 R244_3.1 R244_3.2 R245.1 R245.2 R245_1.1 R245_1.2 R245_1_1.1 R245_1_1.2 R245_2.1 R245_2.2 R245_3.1 R245_3.2 R246.1 R246.2 R246_1.1 R246_1.2 R246_1_1.1 R246_1_1.2 R246_2.1 R246_2.2 R246_3.1 R246_3.2 R247.1 R247.2 R247_1.1 R247_1.2 R247_1_1.1 R247_1_1.2 R247_2.1 R247_2.2 R247_3.1 R247_3.2 R247_3_1.1 R247_3_1.2 R248.1 R248.2 R248_1.1 R248_1.2 R248_1_1.1 R248_1_1.2 R248_2.1 R248_2.2 R248_3.1 R248_3.2 R248_3_1.1 R248_3_1.2 R249.1 R249.2 R249_1.1 R249_1.2 R249_1_1.1 R249_1_1.2 R249_2.1 R249_2.2 R249_3.1 R249_3.2 R249_3_1.1 R249_3_1.2 R250.1 R250.2 R250_1.1 R250_1.2 R250_1_1.1 R250_1_1.2 R250_2.1 R250_2.2 R250_3.1 R250_3.2 R250_3_1.1 R250_3_1.2 R251.1 R251.2 R251_1.1 R251_1.2 R251_1_1.1 R251_1_1.2 R251_2.1 R251_2.2 R251_3.1 R251_3.2 R252.1 R252.2 R252_1.1 R252_1.2 R252_1_1.1 R252_1_1.2 R252_2.1 R252_2.2 R252_3.1 R252_3.2 R252_3_1.1 R252_3_1.2 R253.1 R253.2 R253_1.1 R253_1.2 R253_1_1.1 R253_1_1.2 R253_2.1 R253_2.2 R253_3.1 R253_3.2 R253_3_1.1 R253_3_1.2 R254.1 R254.2 R254_1.1 R254_1.2 R254_1_1.1 R254_1_1.2 R254_2.1 R254_2.2 R254_3.1 R254_3.2 R255.1 R255.2 R255_1.1 R255_1.2 R255_1_1.1 R255_1_1.2 R255_2.1 R255_2.2 R255_3.1 R255_3.2 R256.1 R256.2 R256_1.1 R256_1.2 R256_1_1.1 R256_1_1.2 R256_2.1 R256_2.2 R256_3.1 R256_3.2 R256_3_1.1 R256_3_1.2 R257.1 R257.2 R257_1.1 R257_1.2 R257_1_1.1 R257_1_1.2 R257_2.1 R257_2.2 R257_3.1 R257_3.2 R257_3_1.1 R257_3_1.2 R258.1 R258.2 R258_1.1 R258_1.2 R258_1_1.1 R258_1_1.2 R258_2.1 R258_2.2 R258_3.1 R258_3.2 R259.1 R259.2 R259_1.1 R259_1.2 R259_1_1.1 R259_1_1.2 R259_2.1 R259_2.2 R259_3.1 R259_3.2 R260.1 R260.2 R260_1.1 R260_1.2 R260_1_1.1 R260_1_1.2 R260_2.1 R260_2.2 R260_3.1 R260_3.2 R261.1 R261.2 R261_1.1 R261_1.2 R261_1_1.1 R261_1_1.2 R261_2.1 R261_2.2 R261_3.1 R261_3.2 R262.1 R262.2 R262_1.1 R262_1.2 R262_1_1.1 R262_1_1.2 R262_2.1 R262_2.2 R262_3.1 R262_3.2 R263.1 R263.2 R263_1.1 R263_1.2 R263_1_1.1 R263_1_1.2 R263_2.1 R263_2.2 R263_3.1 R263_3.2 R263_3_1.1 R263_3_1.2 R264.1 R264.2 R264_1.1 R264_1.2 R264_1_1.1 R264_1_1.2 R264_2.1 R264_2.2 R264_3.1 R264_3.2 R264_3_1.1 R264_3_1.2 R264_3_1_1.1 R264_3_1_1.2 R264_3_2.1 R264_3_2.2 R265.1 R265.2 R265_1.1 R265_1.2 R265_1_1.1 R265_1_1.2 R265_2.1 R265_2.2 R265_3.1 R265_3.2 R265_3_1.1 R265_3_1.2 R265_3_1_1.1 R265_3_1_1.2 R265_3_2.1 R265_3_2.2 R266.1 R266.2 R266_1.1 R266_1.2 R266_1_1.1 R266_1_1.2 R266_2.1 R266_2.2 R266_3.1 R266_3.2 R266_3_1.1 R266_3_1.2 R267.1 R267.2 R267_1.1 R267_1.2 R267_1_1.1 R267_1_1.2 R267_2.1 R267_2.2 R267_3.1 R267_3.2 R267_3_1.1 R267_3_1.2 R268.1 R268.2 R268_1.1 R268_1.2 R268_1_1.1 R268_1_1.2 R268_2.1 R268_2.2 R268_3.1 R268_3.2 R269.1 R269.2 R269_1.1 R269_1.2 R269_1_1.1 R269_1_1.2 R269_2.1 R269_2.2 R269_3.1 R269_3.2 R270.1 R270.2 R270_1.1 R270_1.2 R270_1_1.1 R270_1_1.2 R270_2.1 R270_2.2 R270_3.1 R270_3.2 R271.1 R271.2 R271_1.1 R271_1.2 R271_1_1.1 R271_1_1.2 R271_2.1 R271_2.2 R271_3.1 R271_3.2 R271_3_1.1 R271_3_1.2 R271_3_1_1.1 R271_3_1_1.2 R271_3_2.1 R271_3_2.2 R272.1 R272.2 R272_1.1 R272_1.2 R272_1_1.1 R272_1_1.2 R272_2.1 R272_2.2 R272_3.1 R272_3.2 R272_3_1.1 R272_3_1.2 R273.1 R273.2 R273_1.1 R273_1.2 R273_1_1.1 R273_1_1.2 R273_2.1 R273_2.2 R273_3.1 R273_3.2 R273_3_1.1 R273_3_1.2 R274.1 R274.2 R274_1.1 R274_1.2 R274_1_1.1 R274_1_1.2 R274_2.1 R274_2.2 R274_3.1 R274_3.2 R274_3_1.1 R274_3_1.2 R275.1 R275.2 R275_1.1 R275_1.2 R275_1_1.1 R275_1_1.2 R275_2.1 R275_2.2 R275_3.1 R275_3.2 R275_3_1.1 R275_3_1.2 R276.1 R276.2 R276_1.1 R276_1.2 R276_1_1.1 R276_1_1.2 R276_2.1 R276_2.2 R276_3.1 R276_3.2 R276_3_1.1 R276_3_1.2 R276_3_1_1.1 R276_3_1_1.2 R276_3_2.1 R276_3_2.2 R277.1 R277.2 R277_1.1 R277_1.2 R277_1_1.1 R277_1_1.2 R277_2.1 R277_2.2 R277_3.1 R277_3.2 R277_3_1.1 R277_3_1.2 R278.1 R278.2 R278_1.1 R278_1.2 R278_1_1.1 R278_1_1.2 R278_2.1 R278_2.2 R278_3.1 R278_3.2 R278_3_1.1 R278_3_1.2 R279.1 R279.2 R279_1.1 R279_1.2 R279_1_1.1 R279_1_1.2 R279_2.1 R279_2.2 R279_3.1 R279_3.2 R279_3_1.1 R279_3_1.2 R280.1 R280.2 R280_1.1 R280_1.2 R280_1_1.1 R280_1_1.2 R280_2.1 R280_2.2 R280_3.1 R280_3.2 R280_3_1.1 R280_3_1.2 R280_3_1_1.1 R280_3_1_1.2 R280_3_2.1 R280_3_2.2 R281.1 R281.2 R281_1.1 R281_1.2 R281_1_1.1 R281_1_1.2 R281_2.1 R281_2.2 R281_3.1 R281_3.2 R282.1 R282.2 R282_1.1 R282_1.2 R282_1_1.1 R282_1_1.2 R282_2.1 R282_2.2 R282_3.1 R282_3.2 R283.1 R283.2 R283_1.1 R283_1.2 R283_1_1.1 R283_1_1.2 R283_2.1 R283_2.2 R283_3.1 R283_3.2 R284.1 R284.2 R284_1.1 R284_1.2 R284_1_1.1 R284_1_1.2 R284_2.1 R284_2.2 R284_3.1 R284_3.2 R285.1 R285.2 R285_1.1 R285_1.2 R285_1_1.1 R285_1_1.2 R285_2.1 R285_2.2 R285_3.1 R285_3.2 R285_3_1.1 R285_3_1.2 R285_3_1_1.1 R285_3_1_1.2 R285_3_2.1 R285_3_2.2 R286.1 R286.2 R286_1.1 R286_1.2 R286_1_1.1 R286_1_1.2 R286_2.1 R286_2.2 R286_3.1 R286_3.2 R287.1 R287.2 R287_1.1 R287_1.2 R287_1_1.1 R287_1_1.2 R287_2.1 R287_2.2 R287_3.1 R287_3.2 R288.1 R288.2 R288_1.1 R288_1.2 R288_1_1.1 R288_1_1.2 R288_2.1 R288_2.2 R288_3.1 R288_3.2 R289.1 R289.2 R289_1.1 R289_1.2 R289_1_1.1 R289_1_1.2 R289_2.1 R289_2.2 R289_3.1 R289_3.2 R289_3_1.1 R289_3_1.2 R290.1 R290.2 R290_1.1 R290_1.2 R290_1_1.1 R290_1_1.2 R290_2.1 R290_2.2 R290_3.1 R290_3.2 R291.1 R291.2 R291_1.1 R291_1.2 R291_1_1.1 R291_1_1.2 R291_2.1 R291_2.2 R291_3.1 R291_3.2 R291_3_1.1 R291_3_1.2 R292.1 R292.2 R292_1.1 R292_1.2 R292_1_1.1 R292_1_1.2 R292_2.1 R292_2.2 R292_3.1 R292_3.2 R292_3_1.1 R292_3_1.2 R293.1 R293.2 R293_1.1 R293_1.2 R293_1_1.1 R293_1_1.2 R293_2.1 R293_2.2 R293_3.1 R293_3.2 R293_3_1.1 R293_3_1.2 R294.1 R294.2 R294_1.1 R294_1.2 R294_1_1.1 R294_1_1.2 R294_2.1 R294_2.2 R294_3.1 R294_3.2 R294_3_1.1 R294_3_1.2 R295.1 R295.2 R295_1.1 R295_1.2 R295_1_1.1 R295_1_1.2 R295_2.1 R295_2.2 R295_3.1 R295_3.2 R295_3_1.1 R295_3_1.2 R296.1 R296.2 R296_1.1 R296_1.2 R296_1_1.1 R296_1_1.2 R296_2.1 R296_2.2 R296_3.1 R296_3.2 R296_3_1.1 R296_3_1.2 R297.1 R297.2 R297_1.1 R297_1.2 R297_1_1.1 R297_1_1.2 R297_2.1 R297_2.2 R297_3.1 R297_3.2 R297_3_1.1 R297_3_1.2 R298.1 R298.2 R298_1.1 R298_1.2 R298_1_1.1 R298_1_1.2 R298_2.1 R298_2.2 R298_3.1 R298_3.2 R298_3_1.1 R298_3_1.2 R299.1 R299.2 R299_1.1 R299_1.2 R299_1_1.1 R299_1_1.2 R299_2.1 R299_2.2 R299_3.1 R299_3.2 R299_3_1.1 R299_3_1.2 R300.1 R300.2 R300_1.1 R300_1.2 R300_1_1.1 R300_1_1.2 R300_2.1 R300_2.2 R300_3.1 R300_3.2 R301.1 R301.2 R301_1.1 R301_1.2 R301_1_1.1 R301_1_1.2 R301_2.1 R301_2.2 R301_3.1 R301_3.2 R301_3_1.1 R301_3_1.2 R302.1 R302.2 R302_1.1 R302_1.2 R302_1_1.1 R302_1_1.2 R302_2.1 R302_2.2 R302_3.1 R302_3.2 R303.1 R303.2 R303_1.1 R303_1.2 R303_1_1.1 R303_1_1.2 R303_2.1 R303_2.2 R303_3.1 R303_3.2 R304.1 R304.2 R304_1.1 R304_1.2 R304_1_1.1 R304_1_1.2 R304_2.1 R304_2.2 R304_3.1 R304_3.2 R304_3_1.1 R304_3_1.2 R305.1 R305.2 R305_1.1 R305_1.2 R305_1_1.1 R305_1_1.2 R305_2.1 R305_2.2 R305_3.1 R305_3.2 R305_3_1.1 R305_3_1.2 R306.1 R306.2 R306_1.1 R306_1.2 R306_1_1.1 R306_1_1.2 R306_2.1 R306_2.2 R306_3.1 R306_3.2 R307.1 R307.2 R307_1.1 R307_1.2 R307_1_1.1 R307_1_1.2 R307_2.1 R307_2.2 R307_3.1 R307_3.2 R308.1 R308.2 R308_1.1 R308_1.2 R308_1_1.1 R308_1_1.2 R308_2.1 R308_2.2 R308_3.1 R308_3.2 R309.1 R309.2 R309_1.1 R309_1.2 R309_1_1.1 R309_1_1.2 R309_2.1 R309_2.2 R309_3.1 R309_3.2 R310.1 R310.2 R310_1.1 R310_1.2 R310_1_1.1 R310_1_1.2 R310_2.1 R310_2.2 R310_3.1 R310_3.2 R311.1 R311.2 R311_1.1 R311_1.2 R311_2.1 R311_2.2 R311_2_1.1 R311_2_1.2 R312.1 R312.2 R312_1.1 R312_1.2 R312_2.1 R312_2.2 R312_2_1.1 R312_2_1.2 R313.1 R313.2 R313_1.1 R313_1.2 R313_2.1 R313_2.2 R313_2_1.1 R313_2_1.2 R314.1 R314.2 R314_1.1 R314_1.2 R314_2.1 R314_2.2 R314_2_1.1 R314_2_1.2 R315.1 R315.2 R315_1.1 R315_1.2 R315_2.1 R315_2.2 R315_2_1.1 R315_2_1.2 R316.1 R316.2 R316_1.1 R316_1.2 R316_2.1 R316_2.2 R316_2_1.1 R316_2_1.2 R317.1 R317.2 R317_1.1 R317_1.2 R317_2.1 R317_2.2 R317_2_1.1 R317_2_1.2 R318.1 R318.2 R318_1.1 R318_1.2 R318_2.1 R318_2.2 R318_2_1.1 R318_2_1.2 R319.1 R319.2 R319_1.1 R319_1.2 R319_2.1 R319_2.2 R319_2_1.1 R319_2_1.2 R320.1 R320.2 R320_1.1 R320_1.2 R320_2.1 R320_2.2 R320_2_1.1 R320_2_1.2 R321.1 R321.2 R321_1.1 R321_1.2 R321_2.1 R321_2.2 R321_2_1.1 R321_2_1.2 R322.1 R322.2 R322_1.1 R322_1.2 R322_2.1 R322_2.2 R322_2_1.1 R322_2_1.2 R323.1 R323.2 R323_1.1 R323_1.2 R323_2.1 R323_2.2 R323_2_1.1 R323_2_1.2 R324.1 R324.2 R324_1.1 R324_1.2 R324_2.1 R324_2.2 R324_2_1.1 R324_2_1.2 R325.1 R325.2 R325_1.1 R325_1.2 R325_2.1 R325_2.2 R325_2_1.1 R325_2_1.2 R326.1 R326.2 R326_1.1 R326_1.2 R326_2.1 R326_2.2 R326_2_1.1 R326_2_1.2 R327.1 R327.2 R327_1.1 R327_1.2 R327_2.1 R327_2.2 R327_2_1.1 R327_2_1.2 R328.1 R328.2 R328_1.1 R328_1.2 R328_2.1 R328_2.2 R328_2_1.1 R328_2_1.2 R329.1 R329.2 R329_1.1 R329_1.2 R329_2.1 R329_2.2 R329_2_1.1 R329_2_1.2 R330.1 R330.2 R330_1.1 R330_1.2 R330_2.1 R330_2.2 R330_2_1.1 R330_2_1.2 R331.1 R331.2 R331_1.1 R331_1.2 R331_2.1 R331_2.2 R331_2_1.1 R331_2_1.2 R332.1 R332.2 R332_1.1 R332_1.2 R332_2.1 R332_2.2 R332_2_1.1 R332_2_1.2 R333.1 R333.2 R333_1.1 R333_1.2 R333_2.1 R333_2.2 R333_2_1.1 R333_2_1.2 R334.1 R334.2 R334_1.1 R334_1.2 R334_2.1 R334_2.2 R334_2_1.1 R334_2_1.2 R335.1 R335.2 R335_1.1 R335_1.2 R335_2.1 R335_2.2 R335_2_1.1 R335_2_1.2 R336.1 R336.2 R336_1.1 R336_1.2 R336_2.1 R336_2.2 R336_2_1.1 R336_2_1.2 R337.1 R337.2 R337_1.1 R337_1.2 R337_2.1 R337_2.2 R337_2_1.1 R337_2_1.2 R338.1 R338.2 R338_1.1 R338_1.2 R338_2.1 R338_2.2 R338_2_1.1 R338_2_1.2 R339.1 R339.2 R339_1.1 R339_1.2 R339_2.1 R339_2.2 R339_2_1.1 R339_2_1.2 R340.1 R340.2 R340_1.1 R340_1.2 R340_2.1 R340_2.2 R340_2_1.1 R340_2_1.2 R341.1 R341.2 R341_1.1 R341_1.2 R341_2.1 R341_2.2 R341_2_1.1 R341_2_1.2 R342.1 R342.2 R342_1.1 R342_1.2 R342_2.1 R342_2.2 R342_2_1.1 R342_2_1.2 R343.1 R343.2 R343_1.1 R343_1.2 R343_2.1 R343_2.2 R343_2_1.1 R343_2_1.2 R344.1 R344.2 R344_1.1 R344_1.2 R344_2.1 R344_2.2 R344_2_1.1 R344_2_1.2 R345.1 R345.2 R345_1.1 R345_1.2 R345_2.1 R345_2.2 R345_2_1.1 R345_2_1.2 R346.1 R346.2 R346_1.1 R346_1.2 R346_2.1 R346_2.2 R346_2_1.1 R346_2_1.2 R347.1 R347.2 R347_1.1 R347_1.2 R347_2.1 R347_2.2 R347_2_1.1 R347_2_1.2 R348.1 R348.2 R348_1.1 R348_1.2 R348_2.1 R348_2.2 R348_2_1.1 R348_2_1.2 R349.1 R349.2 R349_1.1 R349_1.2 R349_2.1 R349_2.2 R349_2_1.1 R349_2_1.2 R350.1 R350.2 R350_1.1 R350_1.2 R350_2.1 R350_2.2 R350_2_1.1 R350_2_1.2 R351.1 R351.2 R351_1.1 R351_1.2 R351_2.1 R351_2.2 R351_2_1.1 R351_2_1.2 R352.1 R352.2 R352_1.1 R352_1.2 R352_2.1 R352_2.2 R352_2_1.1 R352_2_1.2 R353.1 R353.2 R353_1.1 R353_1.2 R353_2.1 R353_2.2 R353_2_1.1 R353_2_1.2 R354.1 R354.2 R354_1.1 R354_1.2 R354_2.1 R354_2.2 R354_2_1.1 R354_2_1.2 R355.1 R355.2 R355_1.1 R355_1.2 R355_2.1 R355_2.2 R355_2_1.1 R355_2_1.2 R356.1 R356.2 R356_1.1 R356_1.2 R356_2.1 R356_2.2 R356_2_1.1 R356_2_1.2 R357.1 R357.2 R357_1.1 R357_1.2 R357_2.1 R357_2.2 R357_2_1.1 R357_2_1.2 R358.1 R358.2 R358_1.1 R358_1.2 R358_2.1 R358_2.2 R358_2_1.1 R358_2_1.2 R359.1 R359.2 R359_1.1 R359_1.2 R359_2.1 R359_2.2 R359_2_1.1 R359_2_1.2 R360.1 R360.2 R360_1.1 R360_1.2 R360_2.1 R360_2.2 R360_2_1.1 R360_2_1.2 R361.1 R361.2 R361_1.1 R361_1.2 R361_2.1 R361_2.2 R361_2_1.1 R361_2_1.2 R362.1 R362.2 R362_1.1 R362_1.2 R362_2.1 R362_2.2 R362_2_1.1 R362_2_1.2 R363.1 R363.2 R363_1.1 R363_1.2 R363_2.1 R363_2.2 R363_2_1.1 R363_2_1.2 R364.1 R364.2 R364_1.1 R364_1.2 R364_2.1 R364_2.2 R364_2_1.1 R364_2_1.2 R365.1 R365.2 R365_1.1 R365_1.2 R365_2.1 R365_2.2 R365_2_1.1 R365_2_1.2 R366.1 R366.2 R366_1.1 R366_1.2 R366_2.1 R366_2.2 R366_2_1.1 R366_2_1.2 R367.1 R367.2 R367_1.1 R367_1.2 R367_2.1 R367_2.2 R367_2_1.1 R367_2_1.2 R368.1 R368.2 R368_1.1 R368_1.2 R368_2.1 R368_2.2 R368_2_1.1 R368_2_1.2 R369.1 R369.2 R369_1.1 R369_1.2 R369_2.1 R369_2.2 R369_2_1.1 R369_2_1.2 R370.1 R370.2 R370_1.1 R370_1.2 R370_2.1 R370_2.2 R370_2_1.1 R370_2_1.2 R371.1 R371.2 R371_1.1 R371_1.2 R371_2.1 R371_2.2 R371_2_1.1 R371_2_1.2 R372.1 R372.2 R372_1.1 R372_1.2 R372_2.1 R372_2.2 R372_2_1.1 R372_2_1.2 R373.1 R373.2 R373_1.1 R373_1.2 R373_2.1 R373_2.2 R373_2_1.1 R373_2_1.2 R374.1 R374.2 R374_1.1 R374_1.2 R374_2.1 R374_2.2 R374_2_1.1 R374_2_1.2 R375.1 R375.2 R375_1.1 R375_1.2 R375_2.1 R375_2.2 R375_2_1.1 R375_2_1.2 R376.1 R376.2 R376_1.1 R376_1.2 R376_2.1 R376_2.2 R376_2_1.1 R376_2_1.2 R377.1 R377.2 R377_1.1 R377_1.2 R377_2.1 R377_2.2 R377_2_1.1 R377_2_1.2 R378.1 R378.2 R378_1.1 R378_1.2 R378_2.1 R378_2.2 R378_2_1.1 R378_2_1.2 R379.1 R379.2 R379_1.1 R379_1.2 R379_2.1 R379_2.2 R379_2_1.1 R379_2_1.2 R380.1 R380.2 R380_1.1 R380_1.2 R380_2.1 R380_2.2 R380_2_1.1 R380_2_1.2 R381.1 R381.2 R381_1.1 R381_1.2 R381_2.1 R381_2.2 R381_2_1.1 R381_2_1.2 R382.1 R382.2 R382_1.1 R382_1.2 R382_2.1 R382_2.2 R382_2_1.1 R382_2_1.2 R383.1 R383.2 R383_1.1 R383_1.2 R383_2.1 R383_2.2 R383_2_1.1 R383_2_1.2 R384.1 R384.2 R384_1.1 R384_1.2 R384_2.1 R384_2.2 R384_2_1.1 R384_2_1.2 R385.1 R385.2 R385_1.1 R385_1.2 R385_2.1 R385_2.2 R385_2_1.1 R385_2_1.2 R386.1 R386.2 R386_1.1 R386_1.2 R386_2.1 R386_2.2 R386_2_1.1 R386_2_1.2 R387.1 R387.2 R387_1.1 R387_1.2 R387_2.1 R387_2.2 R387_2_1.1 R387_2_1.2 R388.1 R388.2 R388_1.1 R388_1.2 R388_2.1 R388_2.2 R388_2_1.1 R388_2_1.2 R389.1 R389.2 R389_1.1 R389_1.2 R389_2.1 R389_2.2 R389_2_1.1 R389_2_1.2 R390.1 R390.2 R390_1.1 R390_1.2 R390_2.1 R390_2.2 R390_2_1.1 R390_2_1.2 R391.1 R391.2 R391_1.1 R391_1.2 R391_2.1 R391_2.2 R391_2_1.1 R391_2_1.2 R392.1 R392.2 R392_1.1 R392_1.2 R392_2.1 R392_2.2 R392_2_1.1 R392_2_1.2 R393.1 R393.2 R393_1.1 R393_1.2 R393_2.1 R393_2.2 R393_2_1.1 R393_2_1.2 R394.1 R394.2 R394_1.1 R394_1.2 R394_2.1 R394_2.2 R394_2_1.1 R394_2_1.2 R395.1 R395.2 R395_1.1 R395_1.2 R395_2.1 R395_2.2 R395_2_1.1 R395_2_1.2 R396.1 R396.2 R396_1.1 R396_1.2 R396_2.1 R396_2.2 R396_2_1.1 R396_2_1.2 R397.1 R397.2 R397_1.1 R397_1.2 R397_2.1 R397_2.2 R397_2_1.1 R397_2_1.2 R398.1 R398.2 R398_1.1 R398_1.2 R398_2.1 R398_2.2 R398_2_1.1 R398_2_1.2 R399.1 R399.2 R399_1.1 R399_1.2 R399_2.1 R399_2.2 R399_2_1.1 R399_2_1.2 R400.1 R400.2 R400_1.1 R400_1.2 R400_2.1 R400_2.2 R400_2_1.1 R400_2_1.2 R401.1 R401.2 R401_1.1 R401_1.2 R401_2.1 R401_2.2 R401_2_1.1 R401_2_1.2 R402.1 R402.2 R402_1.1 R402_1.2 R402_2.1 R402_2.2 R402_2_1.1 R402_2_1.2 R403.1 R403.2 R403_1.1 R403_1.2 R403_2.1 R403_2.2 R403_2_1.1 R403_2_1.2 R404.1 R404.2 R404_1.1 R404_1.2 R404_2.1 R404_2.2 R404_2_1.1 R404_2_1.2 R405.1 R405.2 R405_1.1 R405_1.2 R405_2.1 R405_2.2 R405_2_1.1 R405_2_1.2 R406.1 R406.2 R406_1.1 R406_1.2 R406_2.1 R406_2.2 R406_2_1.1 R406_2_1.2 R407.1 R407.2 R407_1.1 R407_1.2 R407_2.1 R407_2.2 R407_2_1.1 R407_2_1.2 R408.1 R408.2 R408_1.1 R408_1.2 R408_2.1 R408_2.2 R408_2_1.1 R408_2_1.2 R409.1 R409.2 R409_1.1 R409_1.2 R409_2.1 R409_2.2 R409_2_1.1 R409_2_1.2 R410.1 R410.2 R410_1.1 R410_1.2 R410_2.1 R410_2.2 R410_2_1.1 R410_2_1.2 R411.1 R411.2 R411_1.1 R411_1.2 R412.1 R412.2 R412_1.1 R412_1.2 R413.1 R413.2 R413_1.1 R413_1.2 R414.1 R414.2 R414_1.1 R414_1.2 R415.1 R415.2 R415_1.1 R415_1.2 R416.1 R416.2 R416_1.1 R416_1.2 R417.1 R417.2 R417_1.1 R417_1.2 R418.1 R418.2 R418_1.1 R418_1.2 R418_1_1.1 R418_1_1.2 R418_2.1 R418_2.2 R419.1 R419.2 R419_1.1 R419_1.2 R420.1 R420.2 R420_1.1 R420_1.2 R421.1 R421.2 R421_1.1 R421_1.2 R422.1 R422.2 R422_1.1 R422_1.2 R422_1_1.1 R422_1_1.2 R422_2.1 R422_2.2 R423.1 R423.2 R423_1.1 R423_1.2 R423_1_1.1 R423_1_1.2 R423_2.1 R423_2.2 R424.1 R424.2 R424_1.1 R424_1.2 R425.1 R425.2 R425_1.1 R425_1.2 R426.1 R426.2 R426_1.1 R426_1.2 R426_1_1.1 R426_1_1.2 R426_2.1 R426_2.2 R427.1 R427.2 R427_1.1 R427_1.2 R427_1_1.1 R427_1_1.2 R427_2.1 R427_2.2 R428.1 R428.2 R428_1.1 R428_1.2 R429.1 R429.2 R429_1.1 R429_1.2 R430.1 R430.2 R430_1.1 R430_1.2 R431.1 R431.2 R431_1.1 R431_1.2 R432.1 R432.2 R432_1.1 R432_1.2 R433.1 R433.2 R433_1.1 R433_1.2 R434.1 R434.2 R434_1.1 R434_1.2 R435.1 R435.2 R435_1.1 R435_1.2 R436.1 R436.2 R436_1.1 R436_1.2 R437.1 R437.2 R437_1.1 R437_1.2 R438.1 R438.2 R438_1.1 R438_1.2 R439.1 R439.2 R439_1.1 R439_1.2 R440.1 R440.2 R440_1.1 R440_1.2 R441.1 R441.2 R441_1.1 R441_1.2 R441_1_1.1 R441_1_1.2 R441_2.1 R441_2.2 R442.1 R442.2 R442_1.1 R442_1.2 R443.1 R443.2 R443_1.1 R443_1.2 R444.1 R444.2 R444_1.1 R444_1.2 R445.1 R445.2 R445_1.1 R445_1.2 R446.1 R446.2 R446_1.1 R446_1.2 R447.1 R447.2 R447_1.1 R447_1.2 R447_1_1.1 R447_1_1.2 R447_2.1 R447_2.2 R448.1 R448.2 R448_1.1 R448_1.2 R449.1 R449.2 R449_1.1 R449_1.2 R450.1 R450.2 R450_1.1 R450_1.2 R450_1_1.1 R450_1_1.2 R450_2.1 R450_2.2 R451.1 R451.2 R451_1.1 R451_1.2 R452.1 R452.2 R452_1.1 R452_1.2 R452_1_1.1 R452_1_1.2 R452_2.1 R452_2.2 R453.1 R453.2 R453_1.1 R453_1.2 R454.1 R454.2 R454_1.1 R454_1.2 R455.1 R455.2 R455_1.1 R455_1.2 R456.1 R456.2 R456_1.1 R456_1.2 R457.1 R457.2 R457_1.1 R457_1.2 R458.1 R458.2 R458_1.1 R458_1.2 R459.1 R459.2 R459_1.1 R459_1.2 R460.1 R460.2 R460_1.1 R460_1.2 R461.1 R461.2 R461_1.1 R461_1.2 R462.1 R462.2 R462_1.1 R462_1.2 R463.1 R463.2 R463_1.1 R463_1.2 R463_1_1.1 R463_1_1.2 R463_2.1 R463_2.2 R464.1 R464.2 R464_1.1 R464_1.2 R464_1_1.1 R464_1_1.2 R464_2.1 R464_2.2 R465.1 R465.2 R465_1.1 R465_1.2 R466.1 R466.2 R466_1.1 R466_1.2 R467.1 R467.2 R467_1.1 R467_1.2 R468.1 R468.2 R468_1.1 R468_1.2 R469.1 R469.2 R469_1.1 R469_1.2 R470.1 R470.2 R470_1.1 R470_1.2 R471.1 R471.2 R471_1.1 R471_1.2 R472.1 R472.2 R472_1.1 R472_1.2 R473.1 R473.2 R473_1.1 R473_1.2 R474.1 R474.2 R474_1.1 R474_1.2 R475.1 R475.2 R475_1.1 R475_1.2 R475_1_1.1 R475_1_1.2 R475_2.1 R475_2.2 R476.1 R476.2 R476_1.1 R476_1.2 R477.1 R477.2 R477_1.1 R477_1.2 R478.1 R478.2 R478_1.1 R478_1.2 R479.1 R479.2 R479_1.1 R479_1.2 R480.1 R480.2 R480_1.1 R480_1.2 R481.1 R481.2 R481_1.1 R481_1.2 R482.1 R482.2 R482_1.1 R482_1.2 R483.1 R483.2 R483_1.1 R483_1.2 R484.1 R484.2 R484_1.1 R484_1.2 R484_1_1.1 R484_1_1.2 R484_2.1 R484_2.2 R485.1 R485.2 R485_1.1 R485_1.2 R486.1 R486.2 R486_1.1 R486_1.2 R487.1 R487.2 R487_1.1 R487_1.2 R488.1 R488.2 R488_1.1 R488_1.2 R488_1_1.1 R488_1_1.2 R488_2.1 R488_2.2 R489.1 R489.2 R489_1.1 R489_1.2 R489_1_1.1 R489_1_1.2 R489_2.1 R489_2.2 R490.1 R490.2 R490_1.1 R490_1.2 R491.1 R491.2 R491_1.1 R491_1.2 R492.1 R492.2 R492_1.1 R492_1.2 R493.1 R493.2 R493_1.1 R493_1.2 R494.1 R494.2 R494_1.1 R494_1.2 R495.1 R495.2 R495_1.1 R495_1.2 R496.1 R496.2 R496_1.1 R496_1.2 R497.1 R497.2 R497_1.1 R497_1.2 R498.1 R498.2 R498_1.1 R498_1.2 R498_1_1.1 R498_1_1.2 R498_2.1 R498_2.2 R499.1 R499.2 R499_1.1 R499_1.2 R500.1 R500.2 R500_1.1 R500_1.2 R501.1 R501.2 R501_1.1 R501_1.2 R502.1 R502.2 R502_1.1 R502_1.2 R502_1_1.1 R502_1_1.2 R502_2.1 R502_2.2 R503.1 R503.2 R503_1.1 R503_1.2 R503_1_1.1 R503_1_1.2 R503_2.1 R503_2.2 R504.1 R504.2 R504_1.1 R504_1.2 R505.1 R505.2 R505_1.1 R505_1.2 R506.1 R506.2 R506_1.1 R506_1.2 R507.1 R507.2 R507_1.1 R507_1.2 R508.1 R508.2 R508_1.1 R508_1.2 R508_1_1.1 R508_1_1.2 R508_2.1 R508_2.2 R509.1 R509.2 R509_1.1 R509_1.2 R509_1_1.1 R509_1_1.2 R509_2.1 R509_2.2 R510.1 R510.2 R510_1.1 R510_1.2 R511.1 R511.2 R512.1 R512.2 R513.1 R513.2 R514.1 R514.2 R515.1 R515.2 R516.1 R516.2 R517.1 R517.2 R518.1 R518.2 R519.1 R519.2 R520.1 R520.2 R521.1 R521.2 R522.1 R522.2 R523.1 R523.2 R524.1 R524.2 R525.1 R525.2 R526.1 R526.2 R527.1 R527.2 R528.1 R528.2 R529.1 R529.2 R530.1 R530.2 R531.1 R531.2 R532.1 R532.2 R533.1 R533.2 R534.1 R534.2 R535.1 R535.2 R536.1 R536.2 R537.1 R537.2 R538.1 R538.2 R539.1 R539.2 R540.1 R540.2 R541.1 R541.2 R542.1 R542.2 R543.1 R543.2 R544.1 R544.2 R545.1 R545.2 R546.1 R546.2 R547.1 R547.2 R548.1 R548.2 R549.1 R549.2 R550.1 R550.2 R551.1 R551.2 R552.1 R552.2 R553.1 R553.2 R554.1 R554.2 R555.1 R555.2 R556.1 R556.2 R557.1 R557.2 R558.1 R558.2 R559.1 R559.2 R560.1 R560.2 R561.1 R561.2 R562.1 R562.2 R563.1 R563.2 R564.1 R564.2 R565.1 R565.2 R566.1 R566.2 R567.1 R567.2 R568.1 R568.2 R569.1 R569.2 R570.1 R570.2 R571.1 R571.2 R572.1 R572.2 R573.1 R573.2 R574.1 R574.2 R575.1 R575.2 R576.1 R576.2 R577.1 R577.2 R578.1 R578.2 R579.1 R579.2 R580.1 R580.2 R581.1 R581.2 R582.1 R582.2 R583.1 R583.2 R584.1 R584.2 R585.1 R585.2 R586.1 R586.2 R587.1 R587.2 R588.1 R588.2 R589.1 R589.2 R590.1 R590.2 R591.1 R591.2 R592.1 R592.2 R593.1 R593.2 R594.1 R594.2 R595.1 R595.2 R596.1 R596.2 R597.1 R597.2 R598.1 R598.2 R599.1 R599.2 R600.1 R600.2 R601.1 R601.2 R602.1 R602.2 R603.1 R603.2 R604.1 R604.2 R605.1 R605.2 R606.1 R606.2 R607.1 R607.2 R608.1 R608.2 R609.1 R609.2 R610.1 R610.2 R611.1 R611.2 R612.1 R612.2 R613.1 R613.2 R614.1 R614.2 R615.1 R615.2 R616.1 R616.2 R617.1 R617.2 R618.1 R618.2 R619.1 R619.2 R620.1 R620.2 R621.1 R621.2 R622.1 R622.2 R623.1 R623.2 R624.1 R624.2 R625.1 R625.2 R626.1 R626.2 R627.1 R627.2 R628.1 R628.2 R629.1 R629.2 R630.1 R630.2 R631.1 R631.2 R632.1 R632.2 R633.1 R633.2 R634.1 R634.2 R635.1 R635.2 R636.1 R636.2 R637.1 R637.2 R638.1 R638.2 R639.1 R639.2 R640.1 R640.2 R641.1 R641.2 R642.1 R642.2 R643.1 R643.2 R644.1 R644.2 R645.1 R645.2 R646.1 R646.2 R647.1 R647.2 R648.1 R648.2 R649.1 R649.2 R650.1 R650.2 R651.1 R651.2 R652.1 R652.2 R653.1 R653.2 R654.1 R654.2 VT1.1 VT1.2 VT1.3 VT2.1 VT2.2 VT2.3 VT3.1 VT3.2 VT3.3 VT4.1 VT4.2 VT4.3 VT5.1 VT5.2 VT5.3 VT6.1 VT6.2 VT6.3 VT7.1 VT7.2 VT7.3 VT8.1 VT8.2 VT8.3 VT9.1 VT9.2 VT9.3 VT10.1 VT10.2 VT10.3 VT11.1 VT11.2 VT11.3 VT12.1 VT12.2 VT12.3 VT13.1 VT13.2 VT13.3 VT14.1 VT14.2 VT14.3 VT15.1 VT15.2 VT15.3 VT16.1 VT16.2 VT16.3 VT17.1 VT17.2 VT17.3 VT18.1 VT18.2 VT18.3 VT19.1 VT19.2 VT19.3 XS1.1 XS1.2 XS1.3 XS1.4 XS1.5 XS1.6 XS1.7 XS1.8 XS1.9 XS1.10 XS1.11 XS1.12 XS1.13 XS1.14 XS1.15 XS1.16 XS1.17 XS1.18 XS1.19 XS1.20 XS2.1 XS2.2 XS2.3 XS2.4 XS2.5 XS3.1 XS3.2 XS3.3 XS3.4 XS3.5 XS4. XS4.1 XS4.2 XS4.3 XS4.4 XS4.5 XS4.6 XS4.7 XS4.8 XS4.9 XS4.10 XS4.11 XS4.12 XS4.13 XS4.14 XS4.15 XS4.16 XS4.17 XS4.18 XS4.19 XS4.20 XS4.21 XS4.22 XS4.23 XS4.24 XS4.25 XS4.26 XS4.27 XS4.28 XS4.29 XS4.30 XS4.31 XS4.32 XS4.33 XS4.34 XS4.35 XS4.36 XS4.37 XS4.38 XS4.39 XS4.40 XS4.41 XS4.42 XS4.43 XS4.44 XS4.45 XS4.46 XS4.47 XS4.48 XS5. XS5.1 XS5.2 XS5.3 XS5.4 XS5.5 XS5.6 XS5.7 XS5.8 XS6.1 XS6.2 XS6.3 XS6.4 XS6.5 XS6.6 XS6.7 XS6.8 XS6.9 XS6.10 XS6.11 XS6.12 XS6.13 XS6.14 XS6.15 XS6.16 XS6.17 XS6.18 XS6.19 XS6.20 XS7. XS7.1 XS7.2 XS7.3 XS7.4 XS7.5 XS7.6 XS7.7 XS7.8 XS7.9 XS7.10 XS7.11 XS7.12 XS7.13 XS7.14 XS7.15 XS7.16 XS7.17 XS7.18 XS7.19 XS7.20 XS7.21 XS7.22 XS7.23 XS7.24 XS7.25 XS7.26 XS7.27 XS7.28 XS7.29 XS7.30 XS7.31 XS7.32 XS7.33 XS7.34 XS7.35 XS7.36 XS7.37 XS7.38 XS7.39 XS7.40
